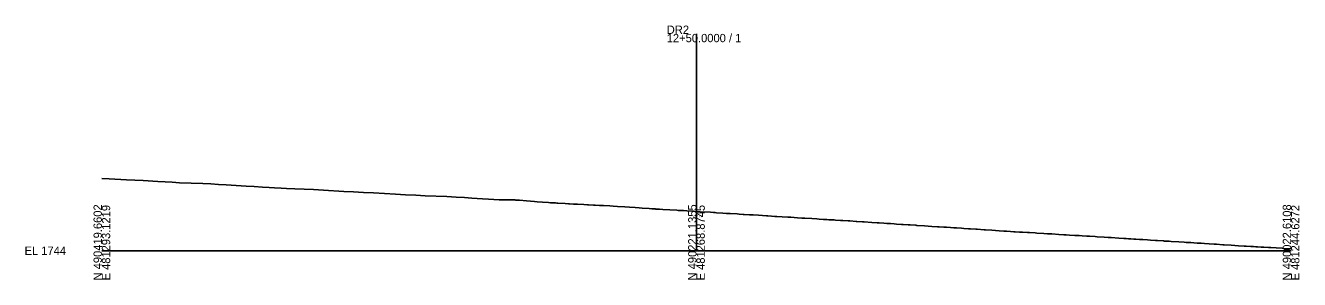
# Model space of a CAD drawing. Extents: x -26 to 403, y -10 to 2576.
# Drawn here: x -25.7 to 402.8, y 2490.3 to 2575.8 of the extents above; entities that cross this region are included whole.
import ezdxf

# ---------------------------------------------------------------- set-up
doc = ezdxf.new("R2010")
doc.units = 0
for name, color, linetype in [('Exist Cross Section Cell', 7, 'Continuous'), ('Exist XS Center Line Elevation Label', 7, 'Continuous'), ('Exist XS Ground Line', 7, 'Continuous')]:
    doc.layers.add(name, color=color, linetype=linetype)

msp = doc.modelspace()

# ---------------------------------------------------------------- linework, layer by layer
at = {"layer": 'Exist Cross Section Cell'}
for p, q in [((200, 2500), (200, 2572.96)), ((0, 2500), (200, 2500)), ((200, 2500), (400, 2500))]:
    msp.add_line(p, q, dxfattribs=at)
at = {"layer": 'Exist XS Ground Line'}
msp.add_lwpolyline([(0, 2524.32), (2.43, 2524.2), (8.32, 2523.89), (11.14, 2523.74), (13.93, 2523.6), (18.8, 2523.29), (21.25, 2523.16), (23.7, 2523.03), (26.13, 2522.9), (34, 2522.61), (36.66, 2522.47), (39.26, 2522.32), (41.82, 2522.17), (48.52, 2521.74), (51.24, 2521.59), (53.98, 2521.44), (56.3, 2521.27), (58.06, 2521.16), (60.28, 2521.04), (62.14, 2520.97), (64.93, 2520.82), (68.02, 2520.72), (71.22, 2520.55), (74.53, 2520.37), (81.39, 2519.97), (84.65, 2519.8), (88.01, 2519.61), (91.39, 2519.43), (98.76, 2519.06), (102.16, 2518.86), (105.56, 2518.66), (108.76, 2518.47), (116.01, 2518.22), (119.19, 2518.03), (122, 2517.86), (124.43, 2517.72), (128.08, 2517.5), (130, 2517.35), (133.63, 2517.14), (134.09, 2517.13), (134.65, 2517.12), (137.66, 2517.1), (138.13, 2517.11), (138.91, 2517.07), (139.28, 2517.05), (139.67, 2517.02), (140.48, 2516.96), (142.87, 2516.77), (144.15, 2516.67), (145.56, 2516.55), (146.47, 2516.48), (148.16, 2516.37), (150.23, 2516.22), (150.86, 2516.17), (152.59, 2516.06), (153.02, 2516.03), (153.33, 2516.01), (155.85, 2515.84), (156.9, 2515.78), (157.33, 2515.76), (158.67, 2515.69), (159.94, 2515.63), (162.09, 2515.51), (163.32, 2515.45), (163.69, 2515.42), (165.36, 2515.37), (165.96, 2515.33), (167.4, 2515.22), (168.32, 2515.22), (168.68, 2515.19), (170.91, 2515.06), (171.97, 2514.95), (173.41, 2514.9), (175.92, 2514.73), (177.44, 2514.63), (179.35, 2514.51), (180.75, 2514.41), (181.74, 2514.34), (184.08, 2514.19), (185.02, 2514.13), (186.06, 2514.06), (186.36, 2514.04), (187.56, 2513.96), (188.68, 2513.9), (191.01, 2513.75), (193.45, 2513.61), (193.88, 2513.59), (195.61, 2513.49), (196.71, 2513.42), (198.98, 2513.28), (200.27, 2513.19), (201.22, 2513.13), (204.74, 2512.92), (205.76, 2512.86), (206.34, 2512.83), (206.78, 2512.8), (208.88, 2512.68), (210.14, 2512.58), (211.28, 2512.53), (213.69, 2512.37), (214.39, 2512.33), (215.75, 2512.24), (216.07, 2512.22), (217.79, 2512.11), (219.12, 2512.03), (220.89, 2511.91), (222.23, 2511.82), (223.59, 2511.73), (224.01, 2511.7), (225.28, 2511.62), (226.37, 2511.57), (227.02, 2511.53), (228.77, 2511.42), (230.7, 2511.3), (231.24, 2511.26), (231.71, 2511.24), (234, 2511.1), (235.44, 2511.01), (236.43, 2510.95), (238.8, 2510.8), (240.49, 2510.7), (241.27, 2510.65), (242.72, 2510.56), (243.84, 2510.48), (244.52, 2510.44), (245.06, 2510.41), (246.34, 2510.34), (246.8, 2510.31), (248.41, 2510.21), (248.86, 2510.18), (249.24, 2510.15), (251.05, 2510.04), (251.55, 2510.01), (253.69, 2509.88), (253.99, 2509.86), (255.89, 2509.74), (256.41, 2509.7), (258.93, 2509.54), (260.78, 2509.41), (261.47, 2509.37), (263.02, 2509.27), (263.99, 2509.2), (265.28, 2509.12), (266.5, 2509.04), (267.26, 2508.99), (269, 2508.87), (269.52, 2508.84), (271.24, 2508.72), (271.91, 2508.67), (273.81, 2508.55), (274.14, 2508.53), (276.74, 2508.36), (279.11, 2508.2), (281.02, 2508.07), (281.61, 2508.04), (283.2, 2507.94), (284.12, 2507.88), (285.4, 2507.79), (286.61, 2507.71), (287.5, 2507.65), (289.15, 2507.55), (289.89, 2507.5), (291.49, 2507.4), (292.13, 2507.36), (293.98, 2507.23), (294.46, 2507.2), (296.73, 2507.07), (297.21, 2507.04), (299.33, 2506.9), (301.78, 2506.74), (303.43, 2506.62), (304.27, 2506.57), (305.61, 2506.49), (306.76, 2506.41), (307.15, 2506.39), (308.62, 2506.3), (309.3, 2506.26), (309.63, 2506.24), (311.3, 2506.14), (312.06, 2506.1), (313.91, 2505.98), (314.44, 2505.95), (316.88, 2505.8), (318.02, 2505.74), (319.49, 2505.65), (321.9, 2505.49), (323.59, 2505.39), (324.4, 2505.34), (325.42, 2505.28), (327.21, 2505.16), (328.67, 2505.09), (329.78, 2505.02), (331.35, 2504.92), (332.23, 2504.87), (334.08, 2504.75), (334.75, 2504.7), (337.1, 2504.55), (338.45, 2504.46), (339.54, 2504.4), (342.03, 2504.23), (343.76, 2504.12), (344.58, 2504.07), (345.28, 2504.03), (346.06, 2503.98), (347.11, 2503.91), (347.74, 2503.88), (349.01, 2503.8), (349.58, 2503.76), (350.16, 2503.73), (351.76, 2503.62), (352.69, 2503.56), (354.35, 2503.46), (355.06, 2503.42), (357.05, 2503.29), (357.4, 2503.26), (358.94, 2503.17), (359.69, 2503.13), (362.22, 2502.97), (364.04, 2502.86), (364.71, 2502.82), (366.3, 2502.72), (367.24, 2502.66), (368.38, 2502.58), (369.74, 2502.49), (370.88, 2502.42), (372.44, 2502.32), (374.18, 2502.21), (374.93, 2502.16), (377.01, 2502.03), (377.48, 2502), (379.82, 2501.85), (382.29, 2501.7), (384.21, 2501.58), (384.84, 2501.54), (386.46, 2501.45), (387.4, 2501.39), (388.12, 2501.34), (388.74, 2501.31), (389.91, 2501.24), (390.87, 2501.17), (392.38, 2501.09), (393.17, 2501.04), (395, 2500.93), (397, 2500.82), (397.46, 2500.8), (400, 2500.65)], dxfattribs=at)

# ---------------------------------------------------------------- texts
at = {"layer": 'Exist Cross Section Cell'}
for s, p in [('DR2', (190, 2572.96)), ('12+50.0000 / 1', (190, 2570.16)), ('EL 1744', (-26, 2498.6))]:
    msp.add_text(s, height=2.8, dxfattribs=at).set_placement(p)
for s, p in [('N 490419.6602', (0, 2490)), ('E 481293.1219', (2.8, 2490)), ('N 490221.1355', (200, 2490)), ('E 481268.8745', (202.8, 2490)), ('N 490022.6108', (400, 2490)), ('E 481244.6272', (402.8, 2490))]:
    msp.add_text(s, height=2.8, rotation=90, dxfattribs=at).set_placement(p)
at = {"layer": 'Exist XS Center Line Elevation Label'}
msp.add_text('1757.21', height=0.75, dxfattribs=at).set_placement((198.18, 2511.21))

doc.saveas('drawing.dxf')
